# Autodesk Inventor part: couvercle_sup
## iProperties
Created: 2011-01
Part Number: couvercle_sup
Document SubType Name: Modeling
Designer: eric
Density: 1 g/cm^3
Mass: 37.8634 g
Surface Area: 769.176 cm^2
Volume: 37.8634 cm^3
Author: eric
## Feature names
1. Base1
